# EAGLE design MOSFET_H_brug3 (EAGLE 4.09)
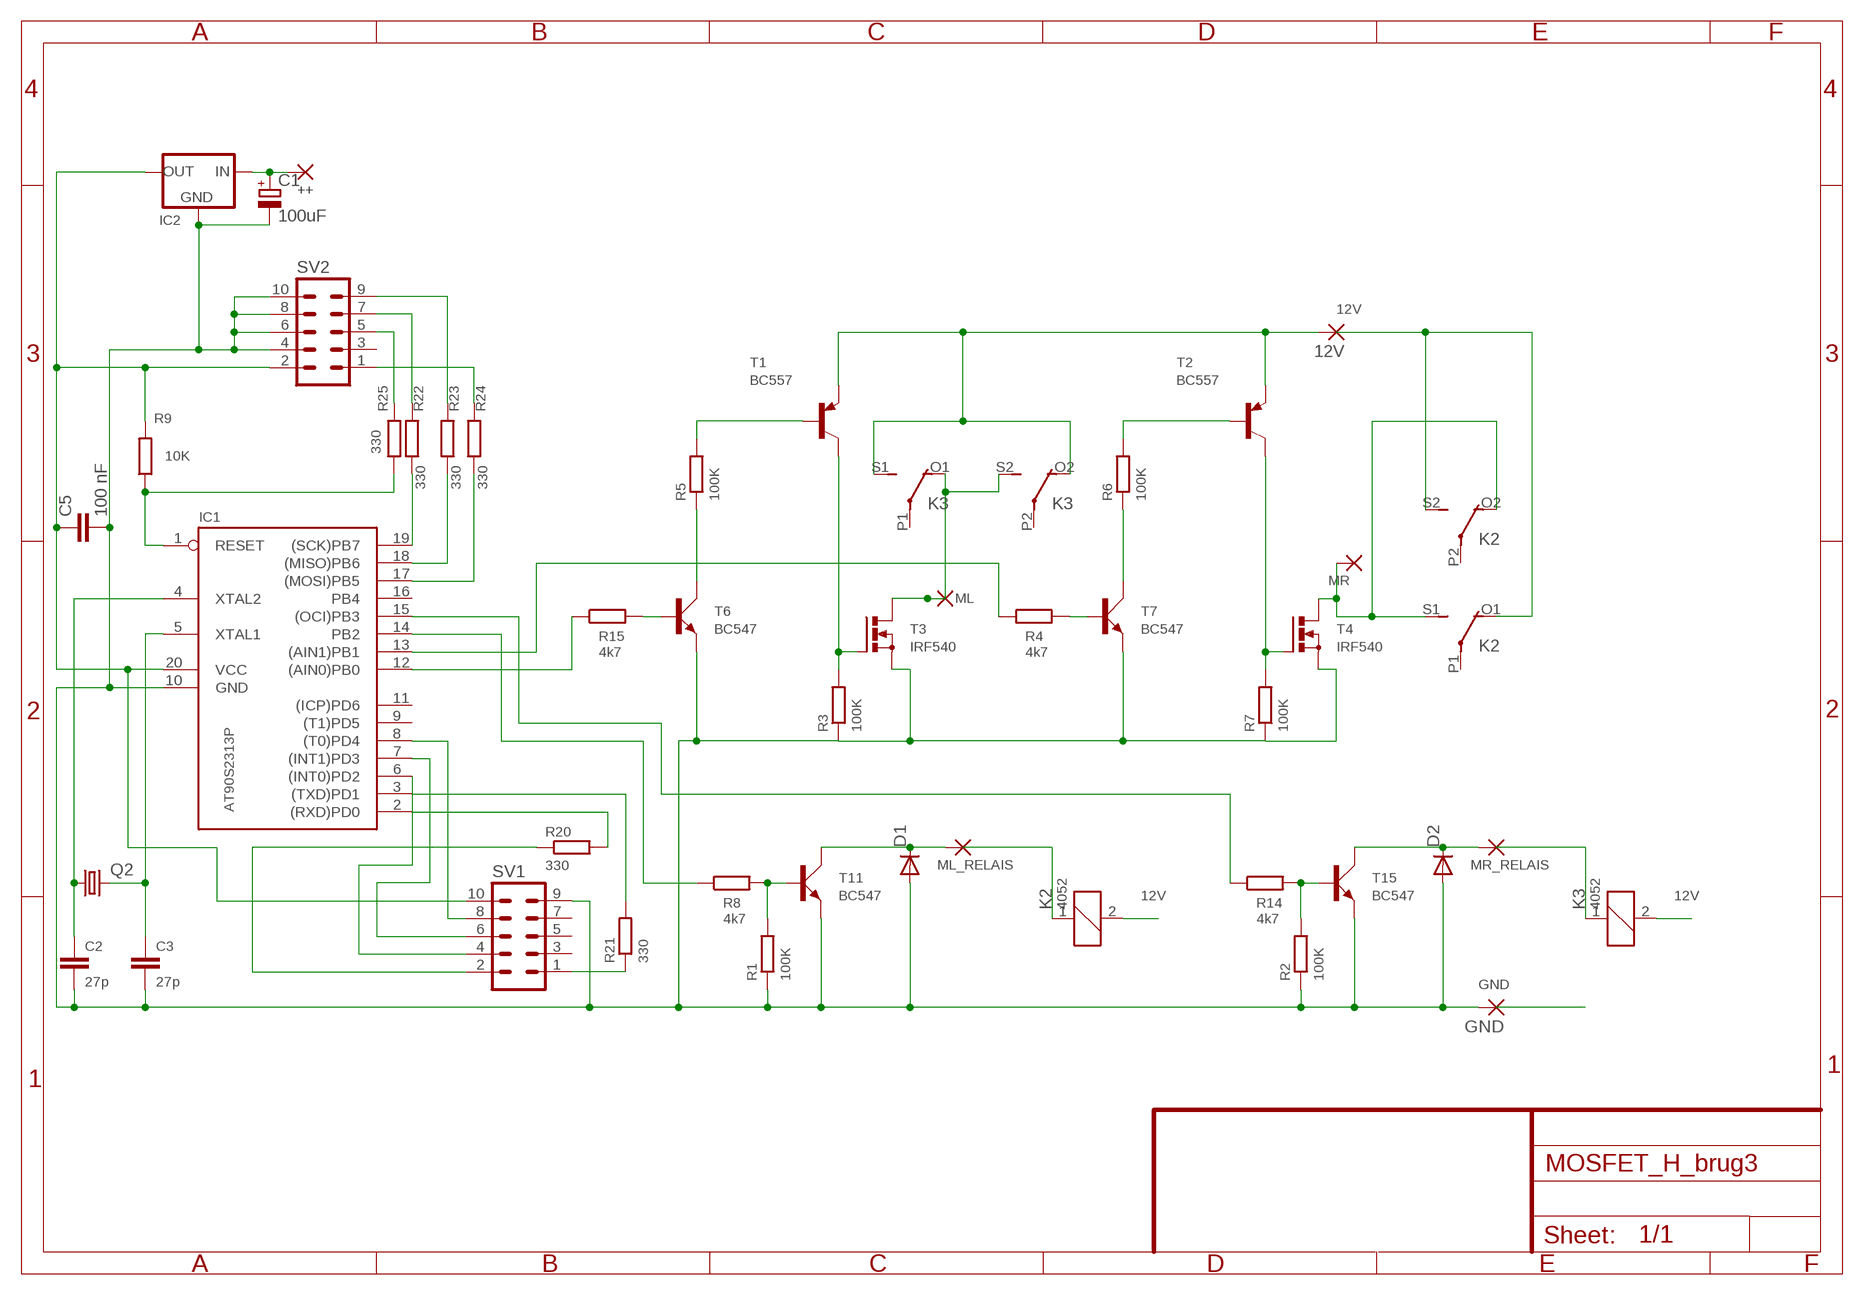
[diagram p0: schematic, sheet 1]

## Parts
12V  2,54/1,0  [2,54/1,0]
++  2,54/1,0  [2,54/1,0]
C1  100uF  CPOL-EUE5-6  [E5-6]
C2  27p  C-EU050-024X044  [C050-024X044]
C3  27p  C-EU050-024X044  [C050-024X044]
C5  100 nF  C-EU075-032X103  [C075-032X103]
D1  DIODE-D-5  [D-5]
D2  DIODE-D-5  [D-5]
GND  2,54/1,0  [2,54/1,0]
IC1  AT90S2313P  [DIL20]
IC2  78XXS  [78XXS]
K2  4052  [F4052]
K3  4052  [F4052]
ML  2,54/1,0  [2,54/1,0]
ML_RELAIS  2,54/1,0  [2,54/1,0]
MR  2,54/1,0  [2,54/1,0]
MR_RELAIS  2,54/1,0  [2,54/1,0]
Q2  CRYTALHC49U-V  [HC49U-V]
R1  100K  R-EU_0204/5  [0204/5]
R2  100K  R-EU_0204/5  [0204/5]
R3  100K  R-EU_0204/5  [0204/5]
R4  4k7  R-EU_0204/5  [0204/5]
R5  100K  R-EU_0207/10  [0207/10]
R6  100K  R-EU_0204/5  [0204/5]
R7  100K  R-EU_0204/5  [0204/5]
R8  4k7  R-EU_0204/5  [0204/5]
R9  10K  R-EU_0204/5  [0204/5]
R14  4k7  R-EU_0204/5  [0204/5]
R15  4k7  R-EU_0204/5  [0204/5]
R20  330  R-EU_0204/7  [0204/7]
R21  330  R-EU_0204/7  [0204/7]
R22  330  R-EU_0204/5  [0204/5]
R23  330  R-EU_0204/5  [0204/5]
R24  330  R-EU_0204/5  [0204/5]
R25  330  R-EU_0204/7  [0204/7]
SV1  MA05-2  [MA05-2]
SV2  MA05-2  [MA05-2]
T1  BC557  [TO92]
T2  BC557  [TO92]
T3  IRF540  [TO220BV]
T4  IRF540  [TO220BV]
T6  BC547  [SOT54A]
T7  BC547  [SOT54A]
T11  BC547  [SOT54A]
T15  BC547  [SOT54A]

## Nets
12V: 12V.1(P) K2.2 K2.O1(2:O) K2.S2(3:S) K3.2 K3.O2(3:O) K3.S1(2:S) T1.1(E) T2.1(E)
GND: C1.- C2.2 C3.2 C5.2 D1.A D2.A GND.1(P) IC1.10(GND) IC2.GND R1.1 R2.1 R3.1 R7.1 SV1.9 SV2.4 SV2.6 SV2.8 SV2.10 T3.S T4.S T6.E T7.E T11.E T15.E
MR: K2.O2(3:O) K2.S1(2:S) MR.1(P) T4.D
N$1: R3.2 T1.3(C) T3.G
N$2: K3.O1(2:O) K3.S2(3:S) ML.1(P) T3.D
N$3: ++.1(P) C1.+ IC2.IN
N$4: D2.C K3.1 MR_RELAIS.1(P) T15.C
N$5: R7.2 T2.3(C) T4.G
N$7: R21.1 SV1.1
N$8: R4.2 T7.B
N$9: R20.1 SV1.2
N$10: IC1.12((AIN0)PB0) R15.1
N$11: IC1.13((AIN1)PB1) R4.1
N$12: IC1.14(PB2) R8.1
N$13: IC1.15((OCI)PB3) R14.1
N$14: IC1.6((INT0)PD2) SV1.4
N$15: R15.2 T6.B
N$16: IC1.7((INT1)PD3) SV1.6
N$17: R5.2 T1.2(B)
N$18: D1.C K2.1 ML_RELAIS.1(P) T11.C
N$19: R1.2 R8.2 T11.B
N$20: R6.2 T2.2(B)
N$21: R5.1 T6.C
N$22: R6.1 T7.C
N$23: C2.1 IC1.4(XTAL2) Q2.1
N$24: IC1.8((T0)PD4) SV1.8
N$27: R2.2 R14.2 T15.B
N$31: C3.1 IC1.5(XTAL1) Q2.2
N$32: IC1.3((TXD)PD1) R21.2
N$35: IC1.2((RXD)PD0) R20.2
N$36: IC1.19((SCK)PB7) R22.1
N$37: IC1.18((MISO)PB6) R23.1
N$38: IC1.17((MOSI)PB5) R24.1
N$39: R24.2 SV2.1
N$40: IC1.1(RESET) R9.1 R25.1
N$41: R25.2 SV2.5
N$42: R22.2 SV2.7
N$43: R23.2 SV2.9
VCC: C5.1 IC1.20(VCC) IC2.OUT R9.2 SV1.10 SV2.2
Unconnected: IC1.9((T1)PD5) IC1.11((ICP)PD6) IC1.16(PB4) K2.P1(2:P) K2.P2(3:P) K3.P1(2:P) K3.P2(3:P) SV1.3 SV1.5 SV1.7 SV2.3

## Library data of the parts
12V ++ GND ML ML_RELAIS MR MR_RELAIS = wirepad:2,54/1,0: THROUGH-HOLE PAD
C1 = rcl:CPOL-EU: POLARIZED CAPACITOR, European symbol
C2 C3 C5 = rcl:C-EU: CAPACITOR, European symbol
D1 D2 = diode:DIODE-: DIODE
IC1 = atmel:AT90S2313: MICROCONTROLLER 2 Kbytes FLASH 128 bytes SRAM 128 bytes EEPROM UART
IC2 = v-reg:78XXS: VOLTAGE REGULATOR
K2 K3 = relay:4052: RELAY 2 x switch, Finder
Q2 = crystal:CRYTAL: CRYSTAL
R1-R9 R14 R15 R20-R25 = rcl:R-EU_: RESISTOR, European symbol
SV1 SV2 = con-lstb:MA05-2: PIN HEADER
T1 T2 = transistor-pnp:BC557: PNP Transistor
T3 T4 = transistor-power:IRF540: N-CHANNEL MOS FET
T6 T7 T11 T15 = transistor-small-signal:BC547: NPN TRANSISTOR

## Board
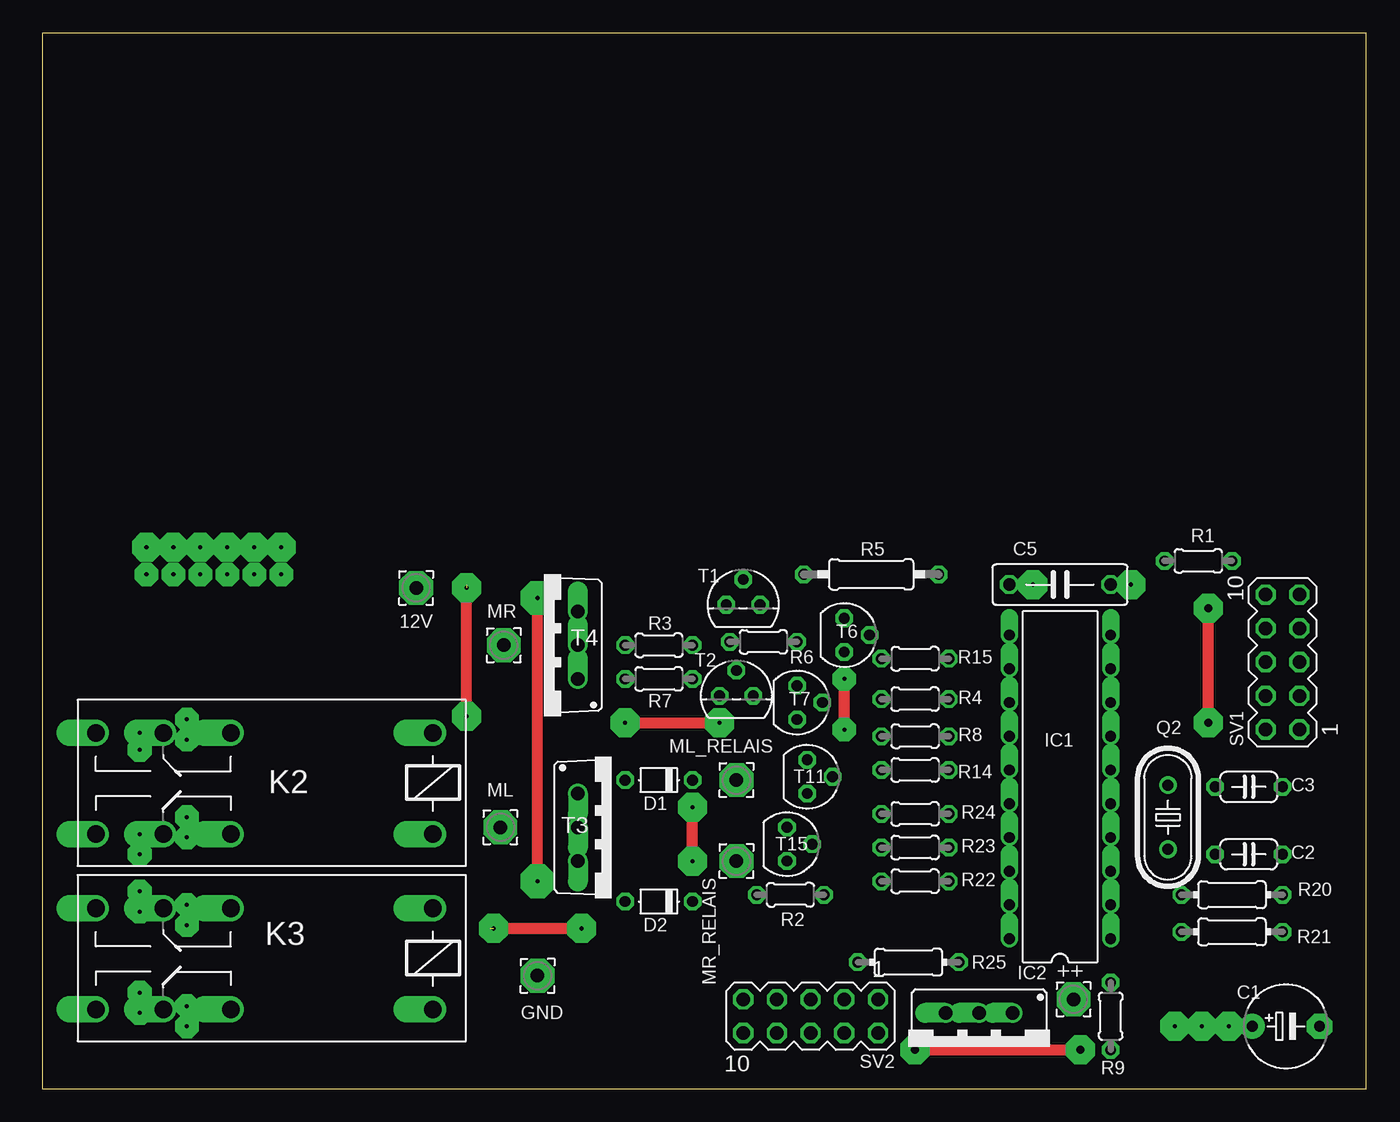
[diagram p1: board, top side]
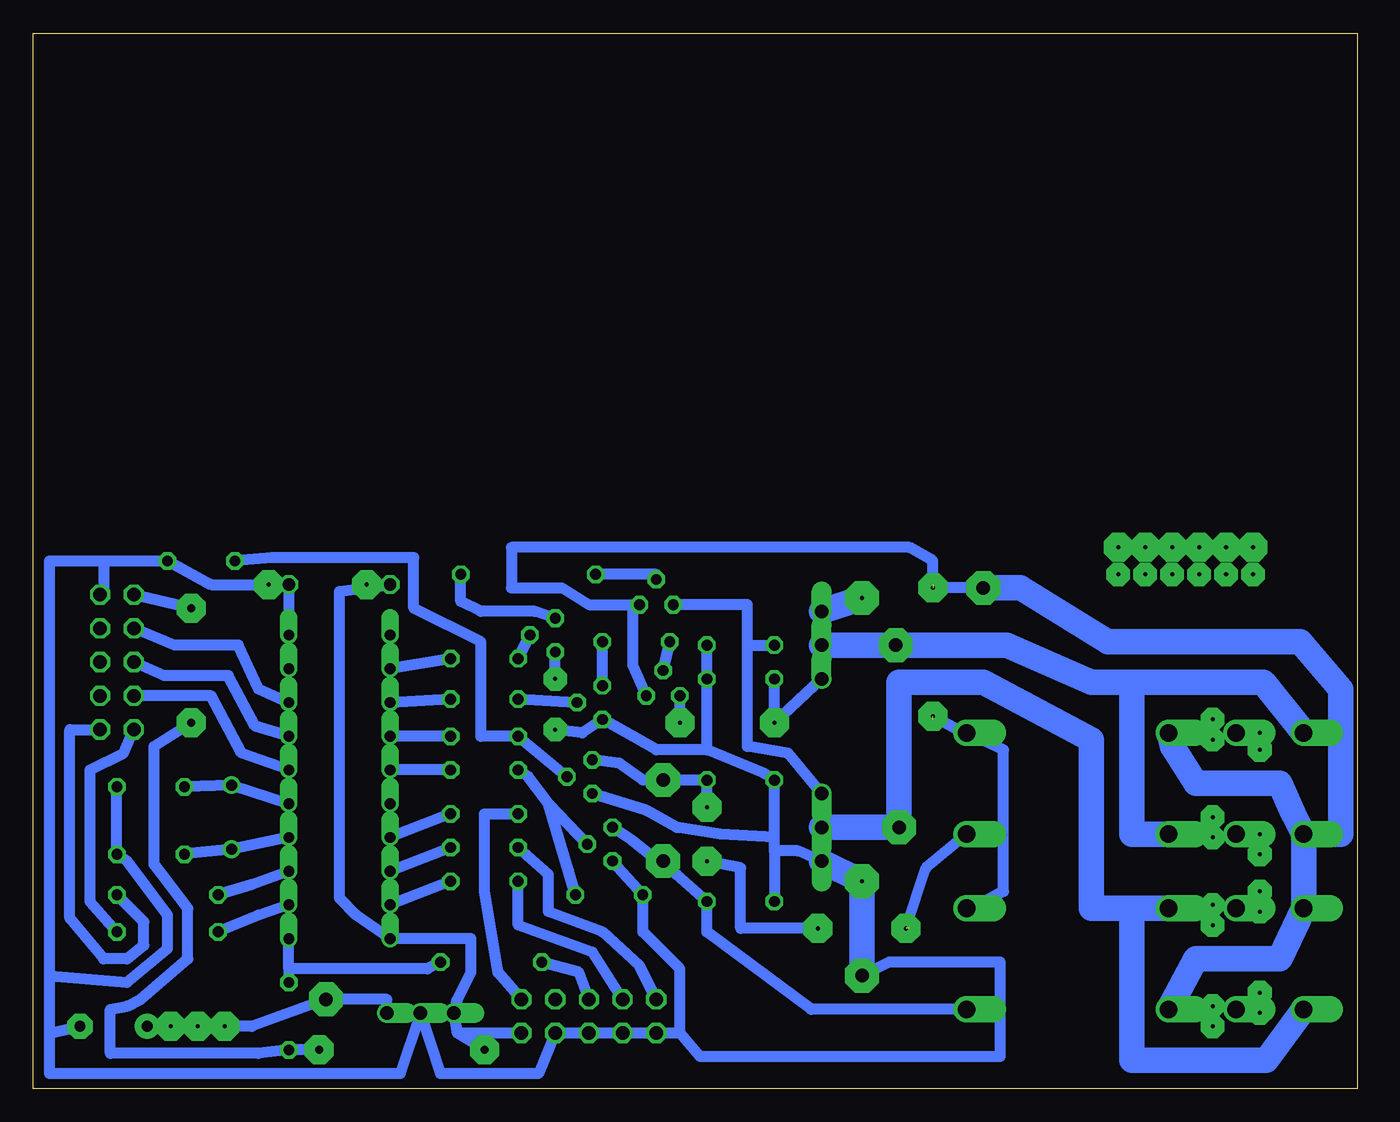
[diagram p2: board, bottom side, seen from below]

Size 99.75 x 79.49 mm. Coordinates in mm from the lower left corner, seen from the top.
Outline: 0,0 99.75,0 99.75,79.49 0,79.49 0,0
Copper layers used: Top, Bottom

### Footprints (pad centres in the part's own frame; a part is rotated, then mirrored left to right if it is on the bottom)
2,54/1,0 = drill 1.016 pad 2.54 octagon: 1 0,0
E5-6 = drill 0.813 pad 1.905 round: + -2.54,0 | drill 0.813 pad 1.905 octagon: - 2.54,0
C050-024X044 = drill 0.813 octagon: 1 -2.54,0; 2 2.54,0
C075-032X103 = drill 0.914 octagon: 1 -3.81,0; 2 3.81,0
D-5 = drill 0.813 octagon: A 2.54,0; C -2.54,0
DIL20 = drill 0.813 offset: 1 -11.43,-3.81; 2 -8.89,-3.81; 3 -6.35,-3.81; 4 -3.81,-3.81; 5 -1.27,-3.81; 6 1.27,-3.81; 7 3.81,-3.81; 8 6.35,-3.81; 9 8.89,-3.81; 10 11.43,-3.81; 11 11.43,3.81; 12 8.89,3.81; 13 6.35,3.81; 14 3.81,3.81; 15 1.27,3.81; 16 -1.27,3.81; 17 -3.81,3.81; 18 -6.35,3.81; 19 -8.89,3.81; 20 -11.43,3.81
78XXS = drill 1.016 offset: GND 0,-2.54; IN -2.54,-2.54; OUT 2.54,-2.54
F4052 = drill 1.321 offset: 1 -3.81,3.81; 2 -3.81,-3.81; O1 11.43,-3.81; O2 11.43,3.81; P1 16.51,-3.81; P2 16.51,3.81; S1 21.59,-3.81; S2 21.59,3.81
HC49U-V = drill 0.813 round: 1 -2.413,0; 2 2.413,0
0204/5 = drill 0.813 octagon: 1 -2.54,0; 2 2.54,0
0207/10 = drill 0.813 octagon: 1 -5.08,0; 2 5.08,0
0204/7 = drill 0.813 octagon: 1 -3.81,0; 2 3.81,0
MA05-2 = drill 1.016 octagon: 1 -5.08,-1.27; 2 -5.08,1.27; 3 -2.54,-1.27; 4 -2.54,1.27; 5 0,-1.27; 6 0,1.27; 7 2.54,-1.27; 8 2.54,1.27; 9 5.08,-1.27; 10 5.08,1.27
TO92 = drill 0.813 octagon: 1 1.27,0; 2 0,1.905; 3 -1.27,0
TO220BV = drill 1.016 offset: D 0,-2.54; G -2.54,-2.54; S 2.54,-2.54
SOT54A = drill 0.813 octagon: B 0,1.905; C -1.27,0; E 1.27,0

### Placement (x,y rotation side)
12V  28.16,37.71 0 top
++  77.69,6.73 0 top
C1  93.69,4.69 0 top
C2  90.89,17.65 0 top
C3  90.89,22.73 0 top
C5  76.67,37.97 0 top
D1  46.44,23.24 180 top
D2  46.44,14.09 180 top
GND  37.3,8.5 0 top
IC1  76.67,22.73 90 top
IC2  70.57,3.17 180 top
K2  25.62,22.98 180 top
K3  25.62,9.77 180 top
ML  34.51,19.68 0 top
ML_RELAIS  52.29,23.24 0 top
MR  34.76,33.4 0 top
MR_RELAIS  52.29,17.14 0 top
Q2  84.8,20.44 90 top
R1  87.08,39.75 180 top
R2  56.35,14.6 0 top
R3  46.44,33.4 180 top
R4  65.75,29.33 180 top
R5  62.45,38.73 180 top
R6  54.32,33.65 180 top
R7  46.44,30.86 180 top
R8  65.75,26.54 180 top
R9  80.48,5.46 270 top
R14  65.75,24 180 top
R15  65.75,32.38 180 top
R20  89.62,11.81 180 top
R21  89.62,14.6 180 top
R22  65.75,15.62 180 top
R23  65.75,18.16 180 top
R24  65.75,20.7 180 top
R25  65.24,9.52 180 top
SV1  93.43,32.13 90 top
SV2  57.87,5.46 180 top
T1  52.79,36.44 0 top
T2  52.29,29.59 0 top
T3  42.89,19.68 270 top
T4  37.81,33.4 90 top
T6  60.41,34.16 270 top
T7  56.86,29.08 270 top
T11  57.62,23.49 270 top
T15  56.1,18.41 270 top

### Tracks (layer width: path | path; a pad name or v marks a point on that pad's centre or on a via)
12V  (via drill 0.3 pad 2.18)  (2 unrouted)
  Top 0.813: 31.97,27.81 31.97,37.97
  Bottom 0.813: T2.1 54.57,31.87 54.57,36.19 T1.1 57.87,36.44 59.91,37.71 63.72,37.71 63.72,40.76 33.74,40.76 31.97,39.75 v31.97,37.71 12V.1 | v31.97,28.06 29.68,26.79 K2.2 26.63,25.52 26.63,14.85 29.43,13.33 K3.2
  Bottom 1.93: K2.O1 13.93,25.78 12.15,22.98 5.8,22.98 4.79,20.7 K2.S2 | K2.S2 K3.S1 5.8,9.77 12.15,9.77 K3.O2 | K2.S2 1.23,19.17 1.23,30.09 4.28,33.65 18.76,33.65 25.36,37.71 12V.1
GND  (via drill 0.3 pad 1.78, 0.3 pad 2.54)
  Top 0.813: v60.41,27.05 v60.41,30.86 | v37.3,15.62 v37.3,36.95
  Bottom 0.813: C3.2 C2.2 92.67,17.14 89.62,13.08 89.62,10.54 92.67,8 98.51,8.5 | 43.9,17.9 D2.A | 43.9,17.9 43.9,18.92 | 43.9,18.92 D1.A 44.67,23.74 48.98,25.52 | T11.E 53.56,20.95 51.27,19.68 47.97,19.17 43.9,18.92 | R3.1 R7.1 48.98,25.52 | v60.41,30.86 T6.E | v60.41,27.05 58.38,26.79 T7.E 52.79,25.52 48.98,25.52 | 94.45,39.75 98.51,39.75 98.51,8.5 | 98.51,4.19 98.51,8.5 | T15.E R2.1 53.81,11.81 51.02,9.01 51.02,4.19 | 51.02,4.19 SV2.10 SV2.8 SV2.6 SV2.4 61.68,1.14 69.05,1.14 IC2.GND 72.1,1.14 98.51,1.14 98.51,4.19 | 51.02,4.19 49.49,2.41 26.89,2.41 26.89,9.52 35.27,9.52 GND.1 | SV1.9 94.45,37.21 94.45,39.75 | 94.45,39.75 R1.1 86.32,37.97 C5.2 IC1.10 | 43.9,17.9 42.13,17.9 T3.S | 98.51,4.19 C1.-
  Bottom 1.93: GND.1 v37.3,15.62 T3.S | v37.3,36.95 T4.S
MR
  Bottom 1.93: K2.O2 16.98,19.17 16.98,30.6 | 16.98,30.6 7.07,30.6 K2.S1 | 16.98,30.6 20.03,30.6 26.38,33.4 MR.1 T4.D
N$1
  Bottom 0.813: 45.94,33.4 45.94,36.44 T1.3 | 45.94,33.4 R3.2 | 45.94,33.4 45.94,25.78 42.89,25.27 T3.G
N$2
  Bottom 1.93: K3.S2 6.82,2.15 16.98,2.15 16.98,13.58 | 16.98,13.58 20.03,13.58 20.03,26.28 28.16,30.6 34.51,30.6 ML.1 T3.D | 16.98,13.58 K3.O1
N$3
  Bottom 0.813: IC2.IN 73.11,6.73 ++.1 83.27,4.69 C1.+
N$4
  Bottom 0.813: T15.C 54.57,18.66 53.3,17.65 MR_RELAIS.1 51.27,16.12 D2.C 48.98,11.81 41.11,5.96 K3.1
N$5  (via drill 0.3 pad 2.18)
  Top 0.813: v43.9,27.55 v51.02,27.55
  Bottom 0.813: R7.2 v43.9,27.55 T4.G | v51.02,27.55 T2.3
N$6  (via drill 0.3 pad 1.78)
  other vias: 7.33,26.79
N$7
  Bottom 0.813: R21.1 91.4,12.57 91.4,10.79 92.67,9.77 94.45,9.77 96.99,12.82 96.99,27.05 SV1.1
N$8
  Bottom 0.813: T7.B 58.89,29.08 R4.2
N$9
  Bottom 0.813: R20.1 95.47,14.09 95.47,24 92.93,25.27 SV1.2
N$10
  Bottom 0.813: R15.1 IC1.12
N$11
  Bottom 0.813: R4.1 IC1.13
N$12
  Bottom 0.813: R8.1 IC1.14
N$13
  Bottom 0.813: R14.1 IC1.15
N$14
  Bottom 0.813: IC1.6 84.04,25.27 86.32,29.59 SV1.4
N$15
  Bottom 0.813: R15.2 T6.B
N$16
  Bottom 0.813: IC1.7 83.02,27.3 85.05,31.11 89.88,31.11 SV1.6
N$17
  Bottom 0.813: T1.2 52.79,38.73 R5.2
N$18  (via drill 0.3 pad 2.18)  (1 unrouted)
  Top 0.813: v48.98,17.14 v48.98,21.2 | 33.74,12.06 v40.6,12.06
  Bottom 0.813: T11.C 55.59,24.51 53.81,23.24 ML_RELAIS.1 D1.C v48.98,21.2 | v48.98,17.14 46.44,16.63 46.44,12.06 v40.6,12.06 | v34,12.06 32.47,16.63 K2.1
N$19
  Bottom 0.813: T11.B R8.2 66,26.54 66,33.65 71.08,36.19 71.08,40 81.75,40 R1.2
N$20
  Bottom 0.813: T2.2 R6.2
N$21
  Bottom 0.813: T6.C 61.94,35.94 66,35.94 67.53,36.7 R5.1
N$22
  Bottom 0.813: T7.C R6.1
N$23
  Bottom 0.813: IC1.4 Q2.1 88.61,17.65 C2.1
N$24
  Bottom 0.813: IC1.8 82.77,30.09 84.29,33.4 89.12,33.4 SV1.8
N$25  (via drill 0.3 pad 2.18)
  other vias: 13.93,40.76
N$26  (via drill 0.3 pad 2.18)
  other vias: 7.84,40.76
N$27
  Bottom 0.813: 60.92,21.46 59.4,16.38 R2.2 | 60.92,21.46 62.45,23.49 R14.2 | 60.92,21.46 T15.B
N$28  (via drill 0.3 pad 1.78)
  other vias: 7.33,25.52
N$29  (via drill 0.3 pad 1.78)
  other vias: 10.88,27.81
N$30  (via drill 0.3 pad 2.18)
  other vias: 82,37.97
N$31
  Bottom 0.813: IC1.5 Q2.2 C3.1
N$32
  Bottom 0.813: IC1.3 83.27,15.36 R21.2
N$33  (via drill 0.3 pad 2.18)
  other vias: 87.34,4.69
N$34  (via drill 0.3 pad 2.18)
  other vias: 85.31,4.69
N$35
  Bottom 0.813: IC1.2 82.77,13.08 R20.2
N$36
  Bottom 0.813: R22.1 IC1.19
N$37
  Bottom 0.813: R23.1 IC1.18
N$38
  Bottom 0.813: R24.1 IC1.17
N$39
  Bottom 0.813: R24.2 65.75,20.7 65.75,14.85 64.73,8.76 SV2.1
N$40
  Bottom 0.813: 80.48,9.01 70.07,9.01 R25.1 | 80.48,9.01 R9.1 | 80.48,9.01 IC1.1
N$41
  Bottom 0.813: R25.2 58.64,8.76 SV2.5
N$42
  Bottom 0.813: SV2.7 57.62,10.28 63.21,12.31 R22.2
N$43
  Bottom 0.813: SV2.9 54.06,9.27 56.86,11.81 60.92,13.33 60.92,16.12 R23.2
N$44  (via drill 0.3 pad 2.18)
  other vias: 74.64,37.97
N$45  (via drill 0.3 pad 1.78)
  other vias: 10.88,12.31
N$46  (via drill 0.3 pad 1.78)
  other vias: 7.33,7.23
N$47  (via drill 0.3 pad 1.78)
  other vias: 7.33,14.85
N$48  (via drill 0.3 pad 2.18)
  other vias: 18,40.76
N$49  (via drill 0.3 pad 2.18)
  other vias: 15.96,40.76
N$50  (via drill 0.3 pad 2.18)
  other vias: 89.37,4.69
N$51  (via drill 0.3 pad 1.78)
  other vias: 18,38.73
N$52  (via drill 0.3 pad 1.78)
  other vias: 15.96,38.73
N$53  (via drill 0.3 pad 1.78)
  other vias: 13.93,38.73
N$66  (via drill 0.3 pad 1.78)
  other vias: 10.88,4.69
N$67  (via drill 0.3 pad 1.78)
  other vias: 10.88,26.28
N$68  (via drill 0.3 pad 1.78)
  other vias: 10.88,18.92
N$69  (via drill 0.3 pad 1.78)
  other vias: 7.33,19.17
N$70  (via drill 0.3 pad 1.78)
  other vias: 10.88,13.84
N$71  (via drill 0.3 pad 1.78)
  other vias: 7.33,17.65
N$72  (via drill 0.3 pad 1.78)
  other vias: 10.88,20.44
N$73  (via drill 0.3 pad 2.18)
  other vias: 11.9,40.76
N$74  (via drill 0.3 pad 2.18)
  other vias: 9.87,40.76
N$75  (via drill 0.3 pad 1.78)
  other vias: 11.9,38.73
N$76  (via drill 0.3 pad 1.78)
  other vias: 9.87,38.73
N$77  (via drill 0.3 pad 1.78)
  other vias: 7.84,38.73
N$90  (via drill 0.3 pad 1.78)
  other vias: 7.33,13.33
N$91  (via drill 0.3 pad 1.78)
  other vias: 10.88,6.22
N$92  (via drill 0.3 pad 1.78)
  other vias: 7.33,5.71
VCC  (via drill 0.61 pad 2.18)
  Top 0.813: v65.75,2.92 v78.19,2.92 | v87.85,27.55 v87.85,36.19
  Bottom 0.813: 67.78,4.19 SV2.2 62.7,4.19 | 67.78,4.19 IC2.OUT 67.78,6.73 66.76,8.76 66.76,11.3 IC1.20 75.4,13.08 76.67,14.35 76.67,37.46 C5.1 | 67.78,4.19 v65.75,2.92 | v78.19,2.92 R9.2 82.77,2.66 93.94,2.66 93.94,5.96 92.67,6.22 91.66,6.73 88.1,9.77 88.1,13.58 90.64,16.89 90.64,25.78 v87.85,27.55 | v87.85,36.19 SV1.10

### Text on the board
tDocu: 2 x 1N4001 = D1, D2 | 6 x 100K = R1,R2,R3,R5,R6,R7 | 1 x 100 nF = C5 | 4 x 4K7 = R4,R8,R14,R15 | 1 x 100 uF = C1 | 6 x 330ohm = R20,R21,R22,R23,R24,R25 | 2 x 27p = C2,C3 | 4 x BC547 = T6,T7,T11,T15 | 2 x BC557 = T1,T2 | 1 x crystal 10Mhz = Q2 | 2 x IRF540 = T3,T4 | 1 x AT90S2313 = IC1 | 1 x 10K = R9
Nets: R19 = ( V+ - 0.2V ) / 0.2 mA | R19 = ( V+ - 0.2V ) / 0.2 mA
Values: R2,R3,R5,R7, = (V+ - 3V) / 0.02 A | R2,R3,R5,R7, = (V+ - 3V) / 0.02 A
